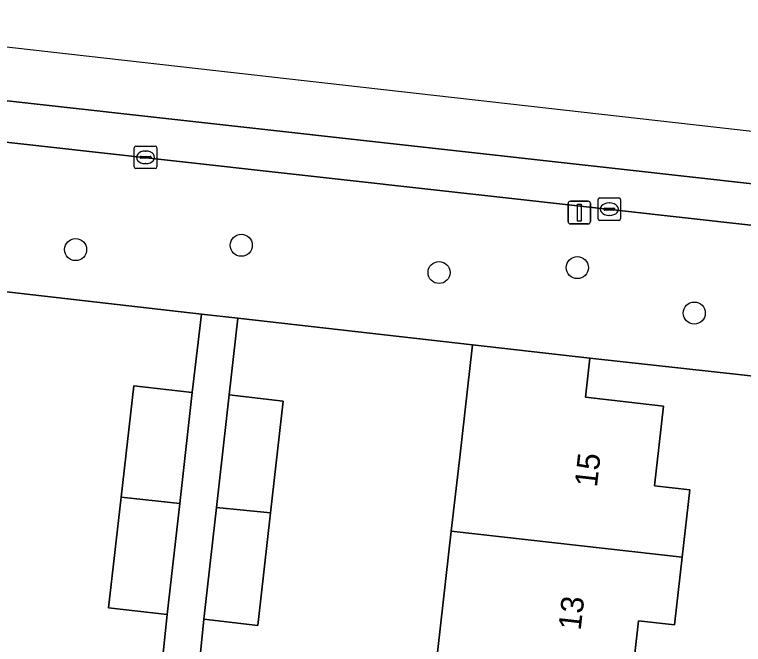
# Model space of a CAD drawing. Extents: x 162082 to 163401, y 388089 to 388636.
# Drawn here: x 162761.73 to 162794.01, y 388544.07 to 388571.98 of the extents above; entities that cross this region are included whole.
import ezdxf

# ---------------------------------------------------------------- set-up
doc = ezdxf.new("R2010")
doc.units = 0
for name, color, linetype in [('IMGEO_Boom', 7, 'Continuous'), ('IMGEO_Erf', 7, 'Continuous'), ('IMGEO_Groenvoorziening', 7, 'Continuous'), ('IMGEO_Kolk', 7, 'Continuous'), ('IMGEO_Lichtmast', 7, 'Continuous'), ('IMGEO_Pand', 7, 'Continuous'), ('IMGEO_Pand_nummerreeks', 7, 'Continuous'), ('IMGEO_Rijbaan_lokaal_gesloten', 7, 'Continuous'), ('IMGEO_Voetpad_open', 7, 'Continuous')]:
    doc.layers.add(name, color=color, linetype=linetype)

msp = doc.modelspace()

# ---------------------------------------------------------------- linework, layer by layer
at = {"layer": 'IMGEO_Boom'}
for centre in [(162764.431, 388561.564), (162771.771, 388561.755), (162786.652, 388560.765), (162780.531, 388560.547), (162791.83, 388558.75)]:
    msp.add_circle(centre, 0.489, dxfattribs=at)
at = {"layer": 'IMGEO_Erf'}
for points in [[(162768.247, 388543.112), (162768.485, 388545.392), (162765.896, 388545.685), (162766.452, 388550.592), (162767.011, 388555.52), (162769.6, 388555.226), (162770.012, 388558.707), (162757.884, 388560.09), (162757.475, 388560.137), (162752.905, 388560.658), (162745.878, 388561.46), (162739.957, 388508.884)], [(162780.357, 388542.8), (162781.07, 388549.092), (162781.442, 388552.371), (162782.005, 388557.339), (162771.615, 388558.524), (162771.232, 388555.125), (162773.63, 388554.853), (162773.068, 388549.895), (162772.504, 388544.912), (162770.105, 388545.184), (162769.883, 388542.803)], [(162795.399, 388555.856), (162787.204, 388556.75), (162787.008, 388555.017), (162790.467, 388554.625), (162790.067, 388551.101), (162791.634, 388550.923), (162791.295, 388547.93), (162790.955, 388544.934), (162789.362, 388545.114), (162788.988, 388541.82)]]:
    msp.add_lwpolyline(points, dxfattribs=at)
at = {"layer": 'IMGEO_Groenvoorziening'}
msp.add_lwpolyline([(162797.242, 388562.316), (162788.394, 388563.304), (162761.06, 388566.354), (162757.762, 388560.635), (162757.947, 388560.613), (162757.884, 388560.09), (162770.012, 388558.707), (162771.615, 388558.524), (162782.005, 388557.339), (162787.204, 388556.75), (162795.399, 388555.856), (162801.378, 388555.202), (162836.053, 388551.411), (162885.731, 388545.91), (162891.85, 388545.225), (162897.573, 388544.584), (162898.152, 388549.754), (162898.22, 388551.047)], close=True, dxfattribs=at)
at = {"layer": 'IMGEO_Kolk'}
for p, q in [((162767.03, 388565.224), (162767.03, 388566.076)), ((162767.105, 388566.15), (162767.957, 388566.15)), ((162767.518, 388565.93), (162767.543, 388565.93)), ((162768.031, 388566.076), (162768.031, 388565.224)), ((162767.289, 388565.644), (162767.289, 388565.656)), ((162767.727, 388565.607), (162767.329, 388565.607)), ((162767.332, 388565.693), (162767.73, 388565.693)), ((162767.773, 388565.656), (162767.773, 388565.644)), ((162767.541, 388565.37), (162767.516, 388565.37)), ((162767.957, 388565.15), (162767.105, 388565.15)), ((162787.569, 388562.927), (162787.569, 388563.779)), ((162787.644, 388563.853), (162788.496, 388563.853)), ((162788.57, 388563.779), (162788.57, 388562.927)), ((162787.828, 388563.347), (162787.828, 388563.359)), ((162787.871, 388563.396), (162788.269, 388563.396)), ((162788.057, 388563.633), (162788.082, 388563.633)), ((162788.312, 388563.359), (162788.312, 388563.347)), ((162788.266, 388563.31), (162787.868, 388563.31)), ((162788.08, 388563.073), (162788.055, 388563.073)), ((162788.496, 388562.853), (162787.644, 388562.853))]:
    msp.add_line(p, q, dxfattribs=at)
for points in [[(162767.03, 388565.224), (162767.03, 388566.076)], [(162767.105, 388566.15), (162767.957, 388566.15)], [(162768.031, 388566.076), (162768.031, 388565.224)], [(162767.957, 388565.15), (162767.105, 388565.15)], [(162787.569, 388562.927), (162787.569, 388563.779)], [(162787.644, 388563.853), (162788.496, 388563.853)], [(162788.57, 388563.779), (162788.57, 388562.927)], [(162788.496, 388562.853), (162787.644, 388562.853)]]:
    msp.add_lwpolyline(points, dxfattribs=at)
for centre, radius, start, end in [((162767.107, 388566.074), 0.0765, 91.552, 178.448), ((162767.107, 388566.074), 0.0765, 91.552, 178.448), ((162767.955, 388566.074), 0.0765, 1.552, 88.448), ((162767.955, 388566.074), 0.0765, 1.552, 88.448), ((162767.329, 388565.653), 0.0403, 85.8775, 175.7526), ((162767.326, 388565.643), 0.0366, 178.938, 274.7102), ((162767.73, 388565.65), 0.043, 264.8664, 352.4533), ((162767.734, 388565.655), 0.0386, 1.7309, 96.639), ((162767.107, 388565.226), 0.0765, 181.552, 268.448), ((162767.107, 388565.226), 0.0765, 181.552, 268.448), ((162767.955, 388565.226), 0.0765, 271.552, 358.448), ((162767.955, 388565.226), 0.0765, 271.552, 358.448), ((162787.646, 388563.777), 0.0765, 91.552, 178.448), ((162787.646, 388563.777), 0.0765, 91.552, 178.448), ((162788.494, 388563.777), 0.0765, 1.552, 88.448), ((162788.494, 388563.777), 0.0765, 1.552, 88.448), ((162787.868, 388563.356), 0.0403, 85.8775, 175.7526), ((162787.865, 388563.346), 0.0366, 178.938, 274.7102), ((162788.269, 388563.353), 0.043, 264.8664, 352.4533), ((162788.273, 388563.358), 0.0386, 1.7309, 96.639), ((162787.646, 388562.929), 0.0765, 181.552, 268.448), ((162787.646, 388562.929), 0.0765, 181.552, 268.448), ((162788.494, 388562.929), 0.0765, 271.552, 358.448), ((162788.494, 388562.929), 0.0765, 271.552, 358.448)]:
    msp.add_arc(centre, radius, start, end, dxfattribs=at)
for centre, major_axis, ratio, start_param, end_param in [((162767.517, 388565.65), (-0.387, 0.002), 0.722429, 4.712389, 7.853982), ((162767.542, 388565.65), (-0.39, 0.002), 0.717154, 1.570796, 4.712389), ((162788.056, 388563.353), (-0.387, 0.002), 0.722429, 4.712389, 7.853982), ((162788.081, 388563.353), (-0.39, 0.002), 0.717154, 1.570796, 4.712389)]:
    msp.add_ellipse(centre, major_axis=major_axis, ratio=ratio, start_param=start_param, end_param=end_param, dxfattribs=at)
at = {"layer": 'IMGEO_Lichtmast'}
for p, q in [((162786.346, 388563.703), (162787.136, 388563.703)), ((162787.136, 388563.703), (162786.346, 388563.703)), ((162786.246, 388562.803), (162786.246, 388563.603)), ((162786.246, 388563.603), (162786.246, 388562.803)), ((162787.236, 388563.603), (162787.236, 388562.803)), ((162787.236, 388562.803), (162787.236, 388563.603)), ((162787.136, 388562.703), (162786.346, 388562.703)), ((162786.346, 388562.703), (162787.136, 388562.703))]:
    msp.add_line(p, q, dxfattribs=at)
msp.add_lwpolyline([(162786.666, 388563.578), (162786.816, 388563.578), (162786.816, 388562.828), (162786.666, 388562.828), (162786.666, 388563.578)], dxfattribs=at)
for centre, start, end in [((162786.346, 388563.603), 90, 180), ((162786.346, 388563.603), 90, 180), ((162787.136, 388563.603), 0, 90), ((162787.136, 388563.603), 360, 90), ((162786.346, 388562.803), 180, 270), ((162786.346, 388562.803), 180, 270), ((162787.136, 388562.803), 270, 0), ((162787.136, 388562.803), 270, 0)]:
    msp.add_arc(centre, 0.1, start, end, dxfattribs=at)
at = {"layer": 'IMGEO_Pand'}
for points in [[(162781.07, 388549.092), (162791.295, 388547.93), (162791.634, 388550.923), (162790.067, 388551.101), (162790.467, 388554.625), (162787.008, 388555.017), (162787.204, 388556.75), (162782.005, 388557.339), (162781.442, 388552.371)], [(162766.452, 388550.592), (162769.042, 388550.307), (162769.6, 388555.226), (162767.011, 388555.52)], [(162770.666, 388550.136), (162773.068, 388549.895), (162773.63, 388554.853), (162771.232, 388555.125)], [(162766.452, 388550.592), (162765.896, 388545.685), (162768.485, 388545.392), (162769.042, 388550.307)], [(162770.666, 388550.136), (162770.105, 388545.184), (162772.504, 388544.912), (162773.068, 388549.895)], [(162780.357, 388542.8), (162788.988, 388541.82), (162789.362, 388545.114), (162790.955, 388544.934), (162791.295, 388547.93), (162781.07, 388549.092)]]:
    msp.add_lwpolyline(points, close=True, dxfattribs=at)
at = {"layer": 'IMGEO_Rijbaan_lokaal_gesloten'}
for points in [[(162898.661, 388555), (162748.571, 388571.976), (162748.313, 388569.613), (162755.69, 388568.792), (162761.263, 388568.173), (162788.597, 388565.123), (162797.445, 388564.135), (162815.695, 388562.098), (162871.917, 388555.824), (162898.423, 388552.866)], [(162815.695, 388562.098), (162797.445, 388564.135), (162788.597, 388565.123), (162761.263, 388568.173), (162755.69, 388568.792), (162748.313, 388569.613), (162748.117, 388567.815), (162749.465, 388567.674), (162750.113, 388567.576), (162761.06, 388566.354), (162788.394, 388563.304), (162797.242, 388562.316), (162898.22, 388551.047), (162898.423, 388552.866), (162871.917, 388555.824)]]:
    msp.add_lwpolyline(points, close=True, dxfattribs=at)
at = {"layer": 'IMGEO_Voetpad_open'}
msp.add_lwpolyline([(162769.883, 388542.803), (162770.105, 388545.184), (162770.666, 388550.136), (162771.232, 388555.125), (162771.615, 388558.524), (162770.012, 388558.707), (162769.6, 388555.226), (162769.042, 388550.307), (162768.485, 388545.392), (162768.247, 388543.112)], dxfattribs=at)

# ---------------------------------------------------------------- texts
at = {"layer": 'IMGEO_Pand_nummerreeks'}
for s, p in [('15', (162787.52, 388551.009)), ('13', (162786.799, 388544.666))]:
    msp.add_text(s, height=1, rotation=83.512, dxfattribs=at).set_placement(p)

doc.saveas('drawing.dxf')
